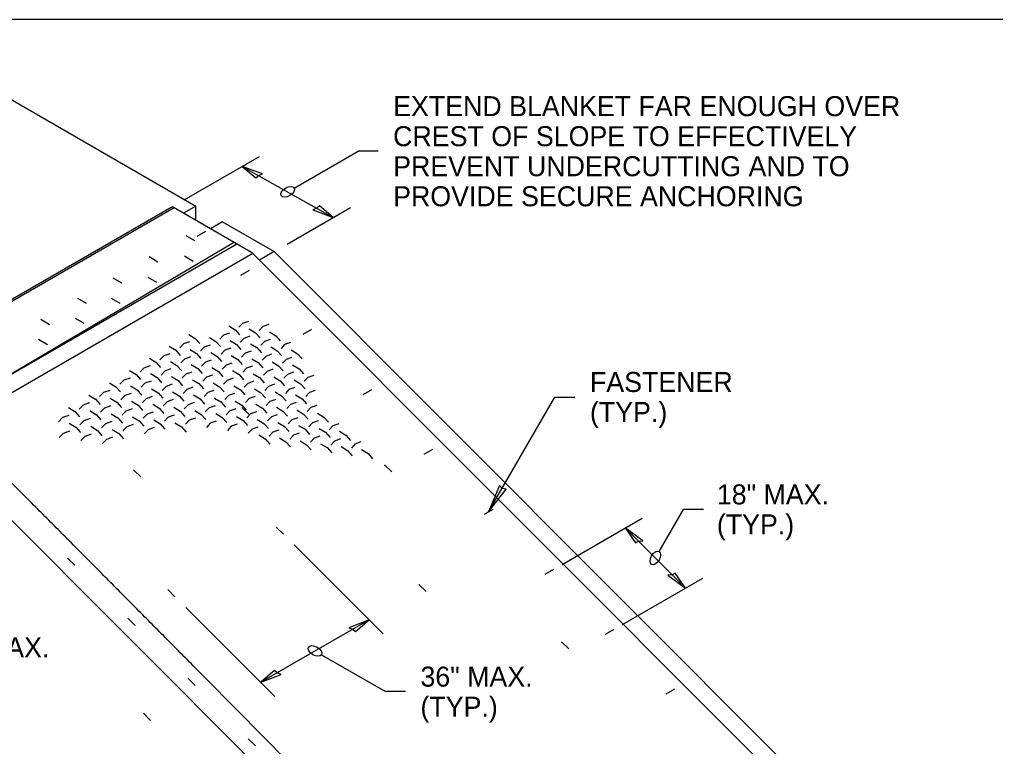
# Model space of a CAD drawing. Extents: x 99862 to 103151, y 100000 to 102076.
# Drawn here: x 101630 to 102411, y 101495 to 102076 of the extents above; entities that cross this region are included whole.
import ezdxf

# ---------------------------------------------------------------- set-up
doc = ezdxf.new("R2010")
doc.units = 0
for name, color, linetype in [('Level 1', 7, 'Continuous'), ('Level 11', 7, 'Continuous'), ('Level 15', 7, 'Continuous'), ('Level 20', 7, 'Continuous'), ('Level 36', 7, 'Continuous'), ('Level 4', 7, 'Continuous'), ('Level 5', 7, 'Continuous'), ('Level 7', 7, 'Continuous')]:
    doc.layers.add(name, color=color, linetype=linetype)

msp = doc.modelspace()

# ---------------------------------------------------------------- linework, layer by layer
at = {"layer": 'Level 1'}
for p, q in [((101602.37, 102023.9), (101771.19, 101926.43)), ((101771.19, 101926.43), (101761.47, 101920.82)), ((101792.73, 101913.85), (101783.12, 101908.3)), ((101792.73, 101913.85), (101833.9, 101890.08)), ((101833.9, 101890.08), (101822.16, 101883.3)), ((102612.56, 101110.84), (101833.9, 101890.08))]:
    msp.add_line(p, q, dxfattribs=at)
msp.add_lwpolyline([(99862, 99999.5), (103151, 99999.5), (103151, 102075.5), (99862, 102075.5)], close=True, dxfattribs=at)
msp.add_lwpolyline([(101771.19, 101915.17), (101771.19, 101926.43)], dxfattribs=at)
at = {"layer": 'Level 11'}
for points in [[(101797.63, 101830.78), (101802.74, 101827.66), (101806.32, 101823.6)], [(101813.41, 101834.2), (101808.74, 101832.58), (101805.79, 101829.53)], [(101813.94, 101828.29), (101819.04, 101825.18), (101822.62, 101821.12)], [(101829.63, 101831.71), (101824.99, 101830.09), (101822.07, 101827.05)], [(101765.76, 101823.87), (101770.9, 101820.73), (101774.48, 101816.64)], [(101782.24, 101821.38), (101787.37, 101818.24), (101790.95, 101814.16)], [(101798.14, 101824.85), (101793.43, 101823.21), (101790.45, 101820.13)], [(101814.47, 101822.36), (101809.79, 101820.73), (101806.84, 101817.65)], [(101830.18, 101825.81), (101835.27, 101822.7), (101838.85, 101818.65)], [(101750.1, 101814.37), (101755.26, 101811.22), (101758.86, 101807.1)], [(101766.22, 101817.89), (101761.45, 101816.24), (101758.4, 101813.13)], [(101782.73, 101815.4), (101777.98, 101813.75), (101774.96, 101810.64)], [(101799.17, 101812.92), (101794.44, 101811.27), (101791.46, 101808.17)], [(101798.65, 101818.89), (101803.77, 101815.76), (101807.36, 101811.69)], [(101815.01, 101816.42), (101820.12, 101813.29), (101823.71, 101809.22)], [(101830.74, 101819.89), (101826.09, 101818.25), (101823.16, 101815.18)], [(101831.3, 101813.95), (101836.4, 101810.83), (101840, 101806.77)], [(101846.95, 101817.42), (101842.32, 101815.79), (101839.42, 101812.72)], [(101734.28, 101804.78), (101739.47, 101801.61), (101743.08, 101797.46)], [(101750.54, 101808.34), (101745.72, 101806.67), (101742.64, 101803.54)], [(101767.16, 101805.86), (101762.36, 101804.19), (101759.31, 101801.06)], [(101766.69, 101811.88), (101771.84, 101808.73), (101775.44, 101804.62)], [(101783.22, 101809.4), (101788.36, 101806.26), (101791.96, 101802.16)], [(101799.68, 101806.93), (101804.82, 101803.79), (101808.42, 101799.7)], [(101815.54, 101810.45), (101810.85, 101808.8), (101807.89, 101805.7)], [(101816.08, 101804.47), (101821.21, 101801.34), (101824.81, 101797.25)], [(101831.86, 101807.99), (101827.19, 101806.34), (101824.26, 101803.24)], [(101848.12, 101805.54), (101843.48, 101803.89), (101840.57, 101800.8)], [(101847.53, 101811.49), (101852.63, 101808.38), (101856.22, 101804.32)], [(101734.7, 101798.7), (101729.84, 101797.01), (101726.73, 101793.85)], [(101750.99, 101802.29), (101756.17, 101799.13), (101759.77, 101794.99)], [(101767.63, 101799.82), (101772.8, 101796.66), (101776.4, 101792.53)], [(101783.71, 101803.39), (101778.94, 101801.72), (101775.92, 101798.59)], [(101784.2, 101797.36), (101789.36, 101794.2), (101792.97, 101790.08)], [(101800.2, 101800.93), (101795.46, 101799.25), (101792.47, 101796.13)], [(101816.62, 101798.47), (101811.91, 101796.8), (101808.95, 101793.68)], [(101832.42, 101802.02), (101837.54, 101798.89), (101841.15, 101794.81)], [(101848.7, 101799.58), (101853.81, 101796.45), (101857.42, 101792.38)], [(101718.71, 101788.97), (101713.8, 101787.25), (101710.65, 101784.06)], [(101718.31, 101795.09), (101723.52, 101791.9), (101727.14, 101787.73)], [(101735.13, 101792.61), (101740.33, 101789.43), (101743.95, 101785.26)], [(101751.43, 101796.23), (101746.6, 101794.54), (101743.51, 101791.37)], [(101751.88, 101790.14), (101757.07, 101786.96), (101760.69, 101782.81)], [(101768.1, 101793.76), (101763.29, 101792.07), (101760.23, 101788.91)], [(101784.7, 101791.3), (101779.92, 101789.61), (101776.89, 101786.46)], [(101801.23, 101788.86), (101796.48, 101787.16), (101793.48, 101784.01)], [(101800.71, 101794.9), (101805.87, 101791.75), (101809.48, 101787.63)], [(101817.16, 101792.45), (101822.31, 101789.31), (101825.92, 101785.2)], [(101832.99, 101796.03), (101828.31, 101794.36), (101825.37, 101791.23)], [(101833.55, 101790.02), (101838.69, 101786.88), (101842.3, 101782.78)], [(101849.29, 101793.59), (101844.64, 101791.92), (101841.72, 101788.8)], [(101865.53, 101791.16), (101860.91, 101789.49), (101858.02, 101786.38)], [(101702.17, 101785.3), (101707.41, 101782.09), (101711.03, 101777.9)], [(101719.1, 101782.83), (101724.33, 101779.63), (101727.96, 101775.44)], [(101735.55, 101786.5), (101730.67, 101784.78), (101727.55, 101781.59)], [(101752.33, 101784.04), (101747.48, 101782.32), (101744.38, 101779.14)], [(101769.04, 101781.58), (101764.22, 101779.87), (101761.15, 101776.69)], [(101768.57, 101787.68), (101773.75, 101784.51), (101777.37, 101780.36)], [(101785.19, 101785.23), (101790.37, 101782.07), (101793.99, 101777.93)], [(101801.75, 101782.79), (101806.92, 101779.63), (101810.54, 101775.5)], [(101817.71, 101786.42), (101812.99, 101784.73), (101810.01, 101781.58)], [(101834.12, 101783.99), (101829.43, 101782.3), (101826.48, 101779.15)], [(101850.47, 101781.57), (101845.8, 101779.88), (101842.88, 101776.73)], [(101849.88, 101787.59), (101855, 101784.46), (101858.62, 101780.36)], [(101685.87, 101775.41), (101691.14, 101772.19), (101694.77, 101767.96)], [(101702.55, 101779.13), (101697.59, 101777.4), (101694.4, 101774.17)], [(101719.5, 101776.67), (101714.58, 101774.93), (101711.42, 101771.71)], [(101736.4, 101774.21), (101731.5, 101772.48), (101728.37, 101769.26)], [(101735.97, 101780.36), (101741.19, 101777.17), (101744.82, 101772.99)], [(101752.77, 101777.91), (101757.99, 101774.72), (101761.62, 101770.55)], [(101769.51, 101775.47), (101774.72, 101772.29), (101778.35, 101768.12)], [(101785.69, 101779.14), (101780.9, 101777.43), (101777.86, 101774.25)], [(101802.28, 101776.71), (101797.51, 101775), (101794.5, 101771.82)], [(101818.8, 101774.29), (101814.06, 101772.58), (101811.08, 101769.4)], [(101818.25, 101780.36), (101823.41, 101777.21), (101827.04, 101773.08)], [(101834.69, 101777.94), (101839.84, 101774.79), (101843.47, 101770.67)], [(101851.06, 101775.53), (101856.2, 101772.38), (101859.83, 101768.27)], [(101866.76, 101779.16), (101862.12, 101777.47), (101859.23, 101774.32)], [(101669.4, 101765.42), (101674.69, 101762.18), (101678.34, 101757.93)], [(101686.22, 101769.19), (101681.22, 101767.44), (101678, 101764.19)], [(101703.3, 101766.74), (101698.33, 101764.98), (101695.13, 101761.73)], [(101702.92, 101772.94), (101708.18, 101769.73), (101711.81, 101765.51)], [(101719.9, 101770.49), (101725.15, 101767.28), (101728.79, 101763.07)], [(101736.82, 101768.04), (101742.06, 101764.84), (101745.7, 101760.64)], [(101753.23, 101771.77), (101748.36, 101770.04), (101745.26, 101766.82)], [(101753.68, 101765.61), (101758.9, 101762.41), (101762.55, 101758.21)], [(101769.99, 101769.33), (101765.15, 101767.6), (101762.08, 101764.39)], [(101786.69, 101766.91), (101781.88, 101765.18), (101778.84, 101761.97)], [(101786.19, 101773.03), (101791.38, 101769.86), (101795.01, 101765.7)], [(101802.8, 101770.61), (101807.98, 101767.44), (101811.62, 101763.29)], [(101819.35, 101768.19), (101824.52, 101765.03), (101828.16, 101760.88)], [(101835.26, 101771.87), (101830.55, 101770.16), (101827.6, 101766.99)], [(101835.83, 101765.79), (101841, 101762.63), (101844.64, 101758.49)], [(101851.66, 101769.47), (101846.98, 101767.76), (101844.05, 101764.59)], [(101867.99, 101767.07), (101863.34, 101765.36), (101860.44, 101762.2)], [(101669.73, 101759.16), (101664.68, 101757.38), (101661.42, 101754.1)], [(101686.57, 101762.96), (101691.85, 101759.73), (101695.5, 101755.49)], [(101703.67, 101760.51), (101708.95, 101757.28), (101712.59, 101753.05)], [(101720.31, 101764.29), (101715.37, 101762.54), (101712.2, 101759.29)], [(101720.71, 101758.07), (101725.97, 101754.85), (101729.62, 101750.62)], [(101737.25, 101761.85), (101732.34, 101760.1), (101729.2, 101756.86)], [(101754.13, 101759.42), (101749.25, 101757.67), (101746.14, 101754.43)], [(101770.47, 101763.18), (101775.68, 101759.99), (101779.33, 101755.8)], [(101787.19, 101760.76), (101792.4, 101757.57), (101796.04, 101753.39)], [(101803.32, 101764.49), (101798.55, 101762.76), (101795.53, 101759.56)], [(101803.85, 101758.35), (101809.05, 101755.17), (101812.7, 101751)], [(101819.9, 101762.08), (101815.15, 101760.35), (101812.16, 101757.15)], [(101836.41, 101759.68), (101831.69, 101757.96), (101828.72, 101754.76)], [(101852.25, 101763.39), (101857.41, 101760.24), (101861.05, 101756.1)], [(101868.61, 101761), (101873.76, 101757.86), (101877.4, 101753.73)], [(101670.06, 101752.87), (101675.36, 101749.62), (101679.02, 101745.36)], [(101686.92, 101756.71), (101681.91, 101754.93), (101678.68, 101751.65)], [(101687.28, 101750.43), (101692.58, 101747.19), (101696.23, 101742.93)], [(101704.05, 101754.27), (101699.07, 101752.49), (101695.86, 101749.22)], [(101721.12, 101751.84), (101716.16, 101750.06), (101712.99, 101746.79)], [(101737.68, 101755.64), (101742.93, 101752.43), (101746.58, 101748.21)], [(101754.59, 101753.22), (101759.83, 101750.01), (101763.48, 101745.8)], [(101770.94, 101757), (101766.1, 101755.25), (101763.01, 101752.02)], [(101787.69, 101754.6), (101782.87, 101752.84), (101779.82, 101749.61)], [(101804.38, 101752.19), (101799.59, 101750.44), (101796.56, 101747.21)], [(101821, 101749.8), (101816.24, 101748.05), (101813.24, 101744.83)], [(101820.45, 101755.95), (101825.64, 101752.78), (101829.29, 101748.61)], [(101836.98, 101753.56), (101842.16, 101750.39), (101845.81, 101746.23)], [(101852.85, 101757.3), (101848.16, 101755.57), (101845.22, 101752.37)], [(101853.45, 101751.18), (101858.62, 101748.02), (101862.28, 101743.86)], [(101869.24, 101754.92), (101864.57, 101753.19), (101861.66, 101749.99)], [(101885.56, 101752.54), (101880.92, 101750.82), (101878.04, 101747.63)], [(101670.38, 101746.57), (101665.32, 101744.78), (101662.05, 101741.47)], [(101687.63, 101744.14), (101682.6, 101742.34), (101679.36, 101739.04)], [(101704.43, 101748), (101709.72, 101744.76), (101713.38, 101740.51)], [(101738.11, 101749.41), (101733.19, 101747.64), (101730.04, 101744.37)], [(101821.56, 101743.63), (101826.76, 101740.45), (101830.42, 101736.26)], [(101837.56, 101747.42), (101832.83, 101745.67), (101829.86, 101742.45)], [(101854.05, 101745.05), (101849.35, 101743.3), (101846.41, 101740.08)], [(101870.49, 101742.68), (101865.81, 101740.94), (101862.89, 101737.72)], [(101869.86, 101748.81), (101875.02, 101745.65), (101878.68, 101741.51)], [(101886.21, 101746.45), (101891.36, 101743.3), (101895.02, 101739.15)], [(101704.81, 101741.72), (101699.82, 101739.92), (101696.6, 101736.62)], [(101838.14, 101741.26), (101843.34, 101738.08), (101847, 101733.9)], [(101854.66, 101738.9), (101859.85, 101735.72), (101863.51, 101731.55)], [(101871.11, 101736.54), (101876.29, 101733.37), (101879.96, 101729.21)], [(101886.86, 101740.33), (101882.21, 101738.58), (101879.32, 101735.37)], [(101887.51, 101734.19), (101892.68, 101731.03), (101896.35, 101726.87)], [(101903.16, 101737.98), (101898.55, 101736.24), (101895.68, 101733.02)], [(101903.84, 101731.85), (101909, 101728.7), (101912.67, 101724.55)]]:
    msp.add_lwpolyline(points, dxfattribs=at)
at = {"layer": 'Level 15'}
for p, q in [((101849.97, 101940.78), (101901.07, 101970.28)), ((101917.07, 101970.28), (101901.07, 101970.28)), ((101761.89, 101931.35), (101822.19, 101966.16)), ((101808.34, 101958.16), (101881.21, 101917.4)), ((101844.26, 101896.06), (101895.07, 101925.4)), ((102005.38, 101681.99), (102058.41, 101773.83)), ((102058.41, 101773.83), (102074.41, 101773.83)), ((102141.66, 101650.39), (102161.07, 101684.01)), ((102177.07, 101684.01), (102161.07, 101684.01)), ((102064.14, 101640.08), (102128.23, 101677.08)), ((102114.58, 101669.2), (102162.74, 101621.18)), ((101850.01, 101655.68), (101921.12, 101584.52)), ((102112.51, 101592.18), (102176.6, 101629.18)), ((101763.45, 101605.7), (101834.56, 101534.55)), ((101909.81, 101595.84), (101823.25, 101545.86)), ((101871.8, 101567.9), (101922.9, 101538.4)), ((101938.9, 101538.4), (101922.9, 101538.4))]:
    msp.add_line(p, q, dxfattribs=at)
for points in [[(101808.34, 101958.16), (101819.41, 101948.91), (101821.43, 101950.84), (101824.71, 101952.06)], [(101881.21, 101917.4), (101870.14, 101926.65), (101868.12, 101924.72), (101864.84, 101923.5)], [(102005.38, 101681.99), (102019.38, 101700.26), (102016.27, 101700.84), (102014.21, 101703.25)], [(102114.58, 101669.2), (102122.74, 101657.29), (102125.2, 101658.61), (102128.69, 101658.9)], [(102162.74, 101621.18), (102154.58, 101633.09), (102152.12, 101631.77), (102148.63, 101631.48)], [(101909.81, 101595.84), (101893.51, 101589.52), (101896.82, 101588.34), (101898.86, 101586.43)], [(101823.25, 101545.86), (101839.54, 101552.19), (101836.24, 101553.36), (101834.2, 101555.27)]]:
    msp.add_lwpolyline(points, close=True, dxfattribs=at)
for centre, major_axis in [((101844.77, 101937.78), (5.2, 3)), ((102138.66, 101645.19), (-3, -5.2)), ((101866.6, 101570.9), (-5.2, 3))]:
    msp.add_ellipse(centre, major_axis=major_axis, ratio=0.57735, dxfattribs=at)
at = {"layer": 'Level 36'}
for p, q in [((101779.18, 101906.1), (101772.18, 101902.08)), ((101763.37, 101902.97), (101770.33, 101898.87)), ((101734.1, 101886.07), (101741.06, 101881.97)), ((101762.17, 101886.6), (101769.12, 101882.5)), ((101814.07, 101875.03), (101807.07, 101871.01)), ((101704.84, 101869.18), (101711.79, 101865.08)), ((101732.9, 101869.71), (101739.86, 101865.61)), ((101676.68, 101852.92), (101683.64, 101848.82)), ((101703.63, 101852.81), (101710.59, 101848.71)), ((101647.42, 101836.03), (101654.37, 101831.92)), ((101674.94, 101836.87), (101681.9, 101832.77)), ((101863.77, 101827.7), (101856.76, 101823.68)), ((101645.67, 101819.97), (101652.63, 101815.87)), ((101911.84, 101779.67), (101904.83, 101775.66)), ((101808.2, 101765.41), (101813.99, 101759.78)), ((101960.51, 101731.9), (101953.5, 101727.88)), ((101922.24, 101719.59), (101928.02, 101713.96)), ((101721.51, 101715.57), (101727.3, 101709.94)), ((102008.88, 101683.99), (102001.88, 101679.98)), ((101835.54, 101669.75), (101841.33, 101664.12)), ((101668.83, 101645.12), (101674.62, 101639.5)), ((102057.25, 101636.09), (102050.25, 101632.08)), ((101748.85, 101619.91), (101754.64, 101614.28)), ((101949.57, 101623.93), (101955.36, 101618.3)), ((101716.98, 101597), (101722.77, 101591.37)), ((102105.62, 101588.19), (102098.62, 101584.17)), ((102063.6, 101578.12), (102069.39, 101572.49)), ((101765.13, 101548.88), (101770.92, 101543.25)), ((102154, 101540.29), (102146.99, 101536.27)), ((101729.41, 101521.1), (101735.2, 101515.47)), ((101813.28, 101500.75), (101819.07, 101495.12))]:
    msp.add_line(p, q, dxfattribs=at)
at = {"layer": 'Level 4'}
msp.add_open_spline([(101953.72, 101371.89), (101768.44, 101560.71), (101576.5, 101752.84)], degree=2, dxfattribs=at)
at = {"layer": 'Level 5'}
for p, q in [((101751.53, 101925.37), (101514.83, 101788.71)), ((101754.03, 101925.12), (101516.29, 101787.86)), ((101815.77, 101889.44), (101754.03, 101925.12)), ((101804.6, 101896.19), (101566.32, 101758.63)), ((101816.91, 101888.55), (101578.49, 101750.9)), ((102599.7, 101105.18), (101816.91, 101888.55))]:
    msp.add_line(p, q, dxfattribs=at)
for centre, start_param, end_param in [((101754.03, 101921.04), 2.356194, 3.141593), ((101815.77, 101885.35), 2.025645, 2.356194)]:
    msp.add_ellipse(centre, major_axis=(2.5, -4.33), ratio=0.57735, start_param=start_param, end_param=end_param, dxfattribs=at)
at = {"layer": 'Level 7'}
for p, q in [((101566.32, 101758.63), (101801.43, 101897.41)), ((102341.08, 100957.72), (101557.51, 101741.88))]:
    msp.add_line(p, q, dxfattribs=at)

# ---------------------------------------------------------------- texts
at = {"layer": 'Level 20'}
for s, p in [('EXTEND BLANKET FAR ENOUGH OVER ', (101929.06, 101998.28)), ('CREST OF SLOPE TO EFFECTIVELY', (101929.06, 101974.28)), ('PREVENT UNDERCUTTING AND TO', (101929.06, 101950.28)), ('PROVIDE SECURE ANCHORING', (101929.06, 101926.28)), ('FASTENER', (102086.41, 101777.83)), ('(TYP.)', (102086.41, 101753.83)), ('18" MAX.', (102187.86, 101688.01)), ('(TYP.)', (102187.86, 101664.01)), ('18" MAX.', (101564.58, 101565.75)), ('36" MAX.', (101950.89, 101542.4)), ('(TYP.)', (101950.89, 101518.4))]:
    msp.add_text(s, height=16, dxfattribs=at).set_placement(p)

doc.saveas('drawing.dxf')
